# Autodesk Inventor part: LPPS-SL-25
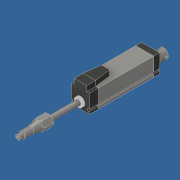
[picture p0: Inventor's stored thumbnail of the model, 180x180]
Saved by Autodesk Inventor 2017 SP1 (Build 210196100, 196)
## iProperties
Created: 2016-12
Part Number: LPPS-SL-25
Material: Stainless Steel
Document SubType Name: Modeling
Designer: JN
Density: 8 g/cm^3
Appearance: Stainless - Brushed
Author: JN
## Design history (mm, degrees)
sketch "Sketch1"
  geometry: C1 r 2.54 at (0, 0)
  constraints: 1 centre point, 1 other
  dimensions: "d0" = 5.08 diameter of C1
extrude "Extrusion1" new body sketch "Sketch1" distance "d1" = 4.572; taper "d2" = 0 deg
sketch "Sketch2"
  geometry: C1 r 3.48 at (0, 0)
  constraints: 1 centre point
  dimensions: "d3" = 6.9596 diameter of C1
extrude "Extrusion2" join sketch "Sketch2" distance "d4" = 8.2042; taper "d5" = 0 deg
workaxis "Work Axis1"
revolve "Revolution2" stored, may be unused: angle "d8" = 90 deg
sketch "Sketch7"
  geometry: L1 (-5.778, 0)-(-2.889, 5.004); L2 (-2.889, 5.004)-(2.889, 5.004); L3 (2.889, 5.004)-(5.778, 0); L4 (5.778, 0)-(2.889, -5.004); L5 (2.889, -5.004)-(-2.889, -5.004); L6 (-2.889, -5.004)-(-5.778, 0); L7 (0, 0)-(0, 8.469); L8 (-0.303, -0.272)-(8.166, -0.272); L9 (0, -3.48)-(0, 0)
  constraints: 18 end point, 3 perpendicular, 1 horizontal, 1 vertical alignment, 14 other
  dimensions: "d20" = 90 deg angle of L8 L7; "d23" = 10.0076 distance between parallel lines of L5 L2
extrude "Extrusion4" join sketch "Sketch7" distance "d21" = 18.03974; taper "d22" = 0 deg
sketch "Sketch8"
  geometry: L1 (3.48, -4.572)-(3.48, -12.776) reference; L2 (0, 1.416)-(0, -21.685); L3 (0, -12.776)-(0, -30.816) reference; L4 (0, 9.356)-(0, -46.226) reference; L5 (5.004, -30.816)-(-5.004, -30.816); L6 (5.004, -30.816)-(0, -30.816) reference; L7 (0, -30.816)-(-5.004, -30.816) reference; L8 (-5.004, -12.776)-(-5.004, -30.816) reference; L9 (-5.004, -30.816)-(-5.004, -12.776); L10 (4.859, -30.943)-(-0.272, -30.943); L11 (-3.48, -12.776)-(3.48, -12.776) reference; L12 (3.48, -4.572)-(3.48, -12.776) reference; L13 (3.48, -12.776)-(3.481, -12.776); L14 (3.481, -12.776)-(9.456, -38.286); L15 (3.481, -12.776)-(9.456, -12.776); L16 (9.456, -38.286)-(9.456, -12.776); A1 r 1.416 centre (0, 0) between (1.416, 0) and (-1.416, 0) reference; 1 further point
  constraints: 16 end point, 2 collinear, 1 horizontal, 1 perpendicular, 1 point on circle, 1 point on line, 1 vertical
revolve "Revolution9" sketch "Sketch8" stored, may be unused: angle "d35" = 90 deg
sketch "Sketch9"
  geometry: C1 r 2.54 at (0, 0)
  constraints: 1 centre point
  dimensions: "d36" = 5.08 diameter of C1
extrude "Extrusion5" join sketch "Sketch9" distance "d37" = 30.48 (= Stroke); taper "d38" = 0 deg
sketch "Sketch10"
  geometry: C1 r 2.54 at (0, 0) reference; C2 r 4.521 at (0, 0)
  constraints: 1 centre point, 1 coincident
  dimensions: "d39" = 9.0424 diameter of C2
extrude "Extrusion6" join sketch "Sketch10" distance "d40" = 2; taper "d41" = 0 deg
sketch "Sketch11"
  geometry: L1 (-9.143, 16.927)-(9.145, 16.927); L2 (9.145, -6.949)-(-9.143, -6.949); L3 (-9.143, -6.949)-(-9.143, 16.927); L4 (-5.778, 0)-(-2.889, -5.004) reference; L5 (5.778, 0)-(2.889, 5.004) reference; L6 (-5.778, 0)-(5.778, 0); L7 (2.889, 5.004)-(-2.889, 5.004) reference; L8 (0, 5.004)-(0, -5.004); L9 (-2.889, -5.004)-(2.889, -5.004) reference; L10 (9.145, -6.949)-(9.145, -4.663); L11 (9.145, -4.663)-(7.621, -4.663); L12 (7.621, -4.663)-(7.621, -2.377); L13 (7.621, -2.377)-(9.145, -2.377); L14 (9.145, 16.927)-(9.145, -2.377); L15 (9.145, -4.663)-(9.145, -6.949); L16 (-9.143, -2.377)-(-7.619, -2.377); L17 (-7.619, -2.377)-(-7.619, -4.663); L18 (-7.619, -4.663)-(-9.143, -4.663)
  constraints: 28 end point, 9 perpendicular, 4 parallel, 4 point on line, 2 horizontal, 2 midpoint
  dimensions: "d42" = 18.288 distance of L1.start L1.end; "d43" = 3.3655 distance from line of L3 L4.start; "d47" = 23.876 distance of L1.end L2.start; "d49" = 1.94564 distance between parallel lines of L2 L9; "d98" = 2.286 distance of L2.start L10.end; "d99" = 1.524 distance of L10.end L11.end; "d100" = 2.286 distance of L11.end L12.end; "d101" = 1.524 distance of L16.start L16.end
extrude "Extrusion7" join sketch "Sketch11" distance "d50" = 9; taper "d51" = 0 deg
sketch "Sketch12"
  geometry: L1 (-9.145, -6.949)-(-9.145, 16.927) reference; L2 (9.143, 16.927)-(9.143, -6.949) reference; L3 (9.143, -6.949)-(-9.145, -6.949) reference; L4 (-9.145, -6.949)-(9.143, -6.949); L5 (-9.145, 16.927)-(9.143, 16.927); L6 (-9.145, 16.927)-(-9.145, -6.949); L7 (-9.145, 16.927)-(9.143, 16.927) reference; L8 (-6.319, 16.927)-(-6.319, 11.593); L9 (6.318, 16.927)-(6.318, 11.593); L10 (-9.145, 11.593)-(-6.319, 11.593); L11 (6.318, 11.593)-(9.143, 11.593)
  constraints: 15 end point, 4 parallel, 2 perpendicular, 2 point on line, 1 collinear
  dimensions: "d52" = 23.876 distance between parallel lines of L4 L5; "d55" = 2.82575 distance between parallel lines of L8 L1; "d56" = 2.82575 distance between parallel lines of L9 L2; "d57" = 18.542 distance between parallel lines of L3 L10; "d58" = 18.542 distance between parallel lines of L3 L11
extrude "Extrusion8" cut sketch "Sketch12" distance "d59" = 9; taper "d60" = 0 deg
mirror "Mirror1"
sketch "Sketch13"
  geometry: L1 (9.145, 11.593)-(6.319, 11.593) reference; L2 (-6.319, 16.927)-(6.319, 16.927); L3 (6.319, 16.927)-(6.319, 11.593); L4 (6.319, 11.593)-(-6.319, 11.593); L5 (-6.319, 11.593)-(-6.319, 16.927)
  constraints: 8 end point, 2 parallel, 1 horizontal, 1 perpendicular
workplane "Work Plane1"
sketch "Sketch14"
  geometry: L1 (6.319, 16.927)-(-6.319, 16.927) reference; L2 (-4.109, 16.927)-(4.121, 16.927); L3 (4.121, 16.927)-(4.121, 11.558); L4 (4.121, 11.558)-(-4.109, 11.558); L5 (-4.109, 11.558)-(-4.109, 16.927); L6 (-6.319, 16.927)-(-6.319, 11.593) reference; L7 (6.319, 11.593)-(6.319, 16.927) reference; 1 further point
  constraints: 8 end point, 2 parallel, 2 perpendicular, 1 horizontal, 1 point on line
  dimensions: "d62" = 8.2296 distance of L3.end L4.end; "d63" = 2.2098 distance between parallel lines of L6 L5; "d65" = 2.6844 distance from line of point (0.006, 14.242) L1; "d66" = 4.1148 distance from line of L5 point (0.006, 14.242)
sketch "3D Sketch1"
loft "Loft1" sketch "3D Sketch1" dims "d67" = 0, "d68" = 90 deg, "d69" = 0, "d70" = 90 deg, "d71" = 0, "d72" = 90 deg
sketch "Sketch15"
  geometry: L1 (-6.319, 11.593)-(-9.143, 11.593) reference; L2 (9.145, -6.949)-(9.145, 11.593) reference; L3 (-9.143, 11.593)-(9.145, 11.593); L4 (9.145, -6.949)-(-9.143, -6.949); L5 (7.621, -2.377)-(9.145, -2.377) reference; L6 (9.145, -2.377)-(7.621, -2.377); L7 (7.621, -4.663)-(7.621, -2.377) reference; L8 (7.621, -2.377)-(7.621, -4.663); L9 (9.145, -4.663)-(7.621, -4.663) reference; L10 (7.621, -4.663)-(9.145, -4.663); L11 (-9.143, -2.377)-(-7.619, -2.377) reference; L12 (-7.619, -4.663)-(-9.143, -4.663) reference; L13 (-9.143, -4.663)-(-7.619, -4.663); L14 (-7.619, -2.377)-(-7.619, -4.663) reference; L15 (-7.619, -4.663)-(-7.619, -2.377); L16 (-9.143, 11.593)-(-9.143, -2.377) reference; L17 (-7.619, -2.377)-(-9.143, -2.377); L18 (9.145, 11.593)-(9.145, -2.377); L19 (9.145, -4.663)-(9.145, -6.949); L20 (-9.143, -6.949)-(-9.143, -4.663); L21 (-9.143, -2.377)-(-9.143, 11.593)
  constraints: 24 end point, 5 parallel, 5 perpendicular, 3 collinear, 1 horizontal
extrude "Extrusion9" new body sketch "Sketch15" distance "d73" = 56.1086 (= Body); taper "d74" = 0 deg
sketch "Sketch16"
  geometry: L1 (-9.143, 11.593)-(-9.143, -6.949) reference; L2 (-9.143, -6.949)-(9.145, -6.949) reference; L3 (-9.143, 11.593)-(9.145, 11.593); L4 (9.145, -6.949)-(-9.143, -6.949); L5 (7.621, -2.377)-(9.145, -2.377) reference; L6 (9.145, -2.377)-(7.621, -2.377); L7 (9.145, -4.663)-(7.621, -4.663) reference; L8 (7.621, -2.377)-(7.621, -4.663); L9 (7.621, -4.663)-(9.145, -4.663); L10 (-9.143, -2.377)-(-7.619, -2.377) reference; L11 (-9.143, -2.377)-(-7.619, -2.377); L12 (-7.619, -2.377)-(-7.619, -4.663) reference; L13 (-7.619, -2.377)-(-7.619, -4.663); L14 (-7.619, -4.663)-(-9.143, -4.663) reference; L15 (-7.619, -4.663)-(-9.143, -4.663); L16 (-9.143, -6.949)-(-9.143, -4.663); L17 (-9.143, -2.377)-(-9.143, 11.593); L18 (9.145, 11.593)-(9.145, -2.377); L19 (9.145, -4.663)-(9.145, -6.949)
  constraints: 24 end point, 5 parallel, 4 perpendicular, 3 collinear, 2 horizontal
extrude "Extrusion10" new body sketch "Sketch16" distance "d75" = 6.0071; taper "d76" = 0 deg
sketch "Sketch17"
  geometry: L1 (-9.143, 11.593)-(9.145, 11.593) reference; L2 (9.145, 11.593)-(9.145, -2.377) reference; L3 (9.145, -6.949)-(-9.143, -6.949) reference; L4 (-9.143, -6.949)-(-9.143, -4.663) reference; L5 (-9.143, -4.663)-(-7.619, -4.663) reference; L6 (-7.619, -4.663)-(-7.619, -2.377) reference; L7 (-7.619, -2.377)-(-9.143, -2.377) reference; L8 (-9.143, -2.377)-(-9.143, 11.593) reference; L9 (9.145, -2.377)-(7.621, -2.377) reference; L10 (7.621, -2.377)-(7.621, -4.663) reference; L11 (7.621, -4.663)-(9.145, -4.663) reference; L12 (9.145, -4.663)-(9.145, -6.949) reference; C1 r 2.54 at (0, 0) reference; C2 r 1.416 at (0, 0) reference; C3 r 4.051 at (0, 0)
  constraints: 1 centre point, 1 coincident
  dimensions: "d77" = 8.1026 diameter of C3
extrude "Extrusion11" new body sketch "Sketch17" distance "d78" = 5; taper "d79" = 0 deg
sketch "Sketch18"
  geometry: C1 r 1.416 at (0, 0) reference; C2 r 5 at (0, 0)
  constraints: 1 centre point, 1 coincident
  dimensions: "d80" = 10 diameter of C2
extrude "Extrusion12" new body sketch "Sketch18" distance "d81" = 8; taper "d82" = 0 deg
shell "Shell2" dims "d84" = 1.397
workaxis "Work Axis4"
workplane "Work Plane2"
sketch "Sketch19"
  geometry: L1 (-5, -8)-(5, -8) reference; L2 (0, -8)-(0, -6.095); 1 further point
  constraints: 2 end point, 1 coincident, 1 midpoint, 1 vertical
  dimensions: "d85" = 1.905 distance of L2.start L2.end
hole "Hole1" sketch "Sketch19" at (0, -6.095) diameter "d86" = 2.3876; stored, may be unused: countersink angle "d90" = 82 deg, drill point angle "d92" = 118 deg; dims "d87" = 19.05, "d88" = 9.525, "d89" = 6.35, "d91" = 25.4
body "Solid1"
sketch "Sketch3"
  geometry: L1 (-2.54, 0)-(2.54, 0) reference; L2 (1.416, 0)-(0, 0); L3 (0, 0)-(0, 1.416); A1 r 1.416 centre (0, 0) between (1.416, 0) and (0, 1.416)
  constraints: 4 end point, 2 point on circle, 1 centre point, 1 midpoint, 1 vertical
  dimensions: "d6" = 2.8321 diameter of A1
body "Solid2"
body "Solid3"
body "Solid4"
body "Solid5"
node "Project Cut Edges1"
other parameters: "Stroke" = 30.48 [user parameter; used in 1 equation term], "Body" = 56.1086 [user parameter; used in 1 equation term], "d53" = 5.334, "d61" = 16.51
